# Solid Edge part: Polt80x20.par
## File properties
Author: Türk
Template: Iso Part.par
Last saved by: Türk
Revision: 11
Application: Solid Edge
Accuracy: 0,990
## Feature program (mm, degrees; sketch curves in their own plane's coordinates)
thread "unnamed Thread 1"
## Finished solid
Body 1: solid body, 23 faces, 45 edges, 24 vertices.
  Faces by surface: plane 21, cylinder 2
  Edges by curve: line 42, circle 3
Bounding box of the edges (mm): 24.000 x 90.000 x 27.713, from (-12, -10, -13.8564) to (12, 80, 13.8564).
Cylindrical faces by radius (mm): R10 x2
Planar faces by outward normal: +x 1, +y 2, -x 1, -y 1, oblique 16
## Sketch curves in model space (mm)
circle centre (0, 0, 0) radius 13.8564
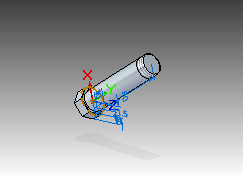
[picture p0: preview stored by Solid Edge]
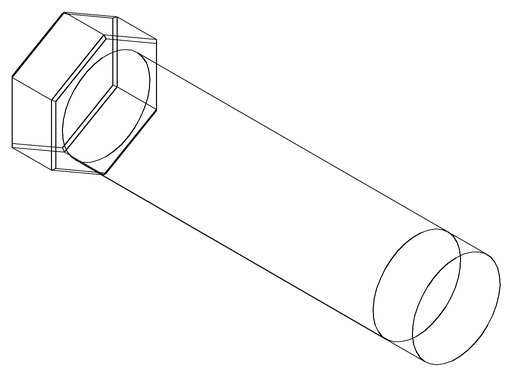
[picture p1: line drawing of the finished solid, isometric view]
